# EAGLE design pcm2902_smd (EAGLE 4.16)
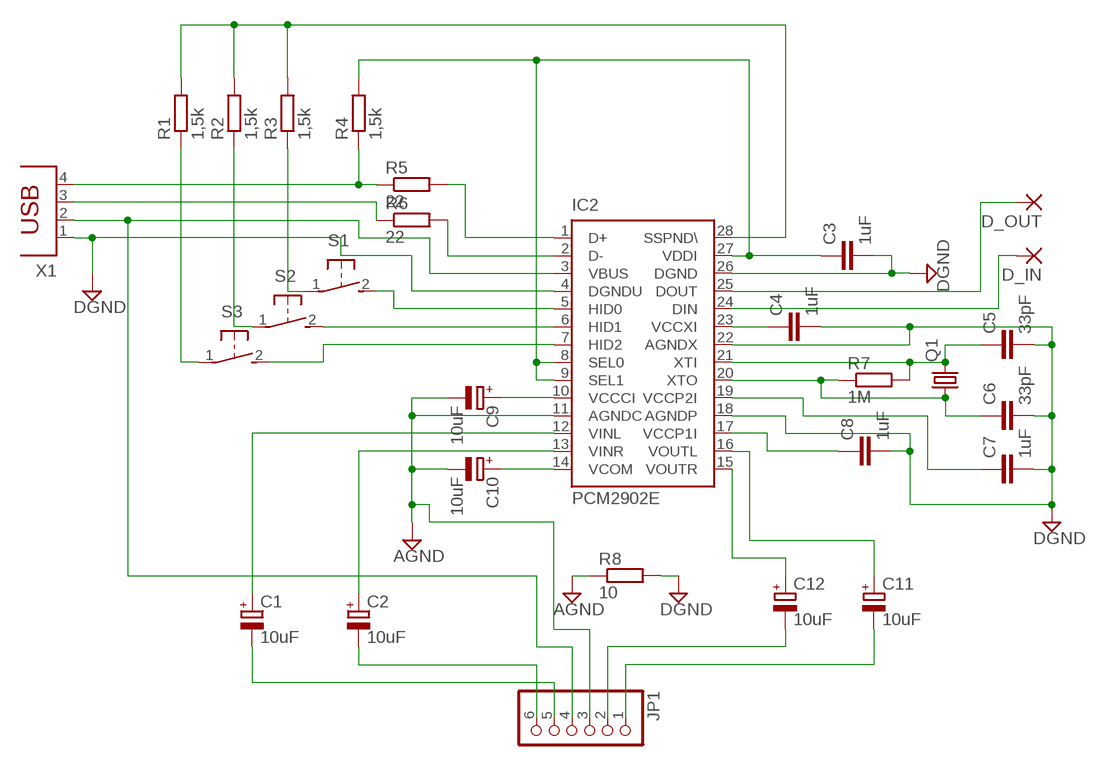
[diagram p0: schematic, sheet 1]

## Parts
C1  10uF  CPOL-EUSMCA  [SMC_A]
C2  10uF  CPOL-EUSMCA  [SMC_A]
C3  1uF  C-EUC1206  [C1206]
C4  1uF  C-EUC1206  [C1206]
C5  33pF  C-EUC1206  [C1206]
C6  33pF  C-EUC1206  [C1206]
C7  1uF  C-EUC1206  [C1206]
C8  1uF  C-EUC1206  [C1206]
C9  10uF  CPOL-EUSMCA  [SMC_A]
C10  10uF  CPOL-EUSMCA  [SMC_A]
C11  10uF  CPOL-EUSMCA  [SMC_A]
C12  10uF  CPOL-EUSMCA  [SMC_A]
D_IN  1,6/0,8  [1,6/0,8]
D_OUT  1,6/0,8  [1,6/0,8]
IC2  PCM2902E  [SSOP28DB]
JP1  PINHD-1X6  [1X06]
Q1  CRYTALSM49  [SM49]
R1  1,5k  R-EU_R1206  [R1206]
R2  1,5k  R-EU_R1206  [R1206]
R3  1,5k  R-EU_R1206  [R1206]
R4  1,5k  R-EU_R1206  [R1206]
R5  22  R-EU_R1206  [R1206]
R6  22  R-EU_R1206  [R1206]
R7  1M  R-EU_R1206  [R1206]
R8  10  R-EU_R1206  [R1206]
S1  31-XX  [B3F-31XX]
S2  31-XX  [B3F-31XX]
S3  31-XX  [B3F-31XX]
X1  PN87520  [PN87520]

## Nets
AGND: C9.- C10.- IC2.11(AGNDC) JP1.3 R8.1
D_OUT: D_OUT.1(P) IC2.25(DOUT)
DGND: C3.2 C4.2 C5.2 C6.2 C7.2 C8.2 IC2.4(DGNDU) IC2.18(AGNDP) IC2.22(AGNDX) IC2.26(DGND) R8.2 X1.1
N$1: C10.+ IC2.14(VCOM)
N$2: C9.+ IC2.10(VCCCI)
N$3: IC2.1(D+) R5.2
N$4: R4.1 R5.1 X1.4
N$5: R6.1 X1.3
N$6: IC2.2(D-) R6.2
N$7: IC2.6(HID1) S2.2(S)
N$8: C3.1 IC2.8(SEL0) IC2.9(SEL1) IC2.27(VDDI) R4.2
N$9: IC2.7(HID2) S3.2(S)
N$10: IC2.5(HID0) S1.2(S)
N$11: R1.1 S3.1(P)
N$12: R2.1 S2.1(P)
N$13: R3.1 S1.1(P)
N$14: C4.1 IC2.23(VCCXI)
N$15: IC2.28(SSPND\) R1.2 R2.2 R3.2
N$16: C1.+ IC2.12(VINL)
N$17: C2.+ IC2.13(VINR)
N$18: C5.1 IC2.21(XTI) Q1.2 R7.2
N$19: C6.1 IC2.20(XTO) Q1.1 R7.1
N$20: C7.1 IC2.19(VCCP2I)
N$21: C8.1 IC2.17(VCCP1I)
N$22: C11.- JP1.1
N$23: D_IN.1(P) IC2.24(DIN)
N$24: C11.+ IC2.16(VOUTL)
N$25: C12.+ IC2.15(VOUTR)
N$26: IC2.3(VBUS) JP1.4 X1.2
N$27: C12.- JP1.2
N$28: C1.- JP1.5
N$29: C2.- JP1.6

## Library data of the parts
C1 C2 C9-C12 = rcl:CPOL-EU: POLARIZED CAPACITOR, European symbol
C3-C8 = rcl:C-EU: CAPACITOR, European symbol
D_IN D_OUT = wirepad:1,6/0,8: THROUGH-HOLE PAD
IC2 = texas:PCM290*: STEREO AUDIO CODEC WITH USB INTERFACE SINGLE-ENDED ANALOG INPUT/OUTPUT AND S/PDIF
JP1 = pinhead:PINHD-1X6: PIN HEADER
Q1 = crystal:CRYTAL: CRYSTAL
R1-R8 = rcl:R-EU_: RESISTOR, European symbol
S1-S3 = switch-omron:31-XX: OMRON SWITCH
X1 = con-berg:PN87520: BERG USB connector

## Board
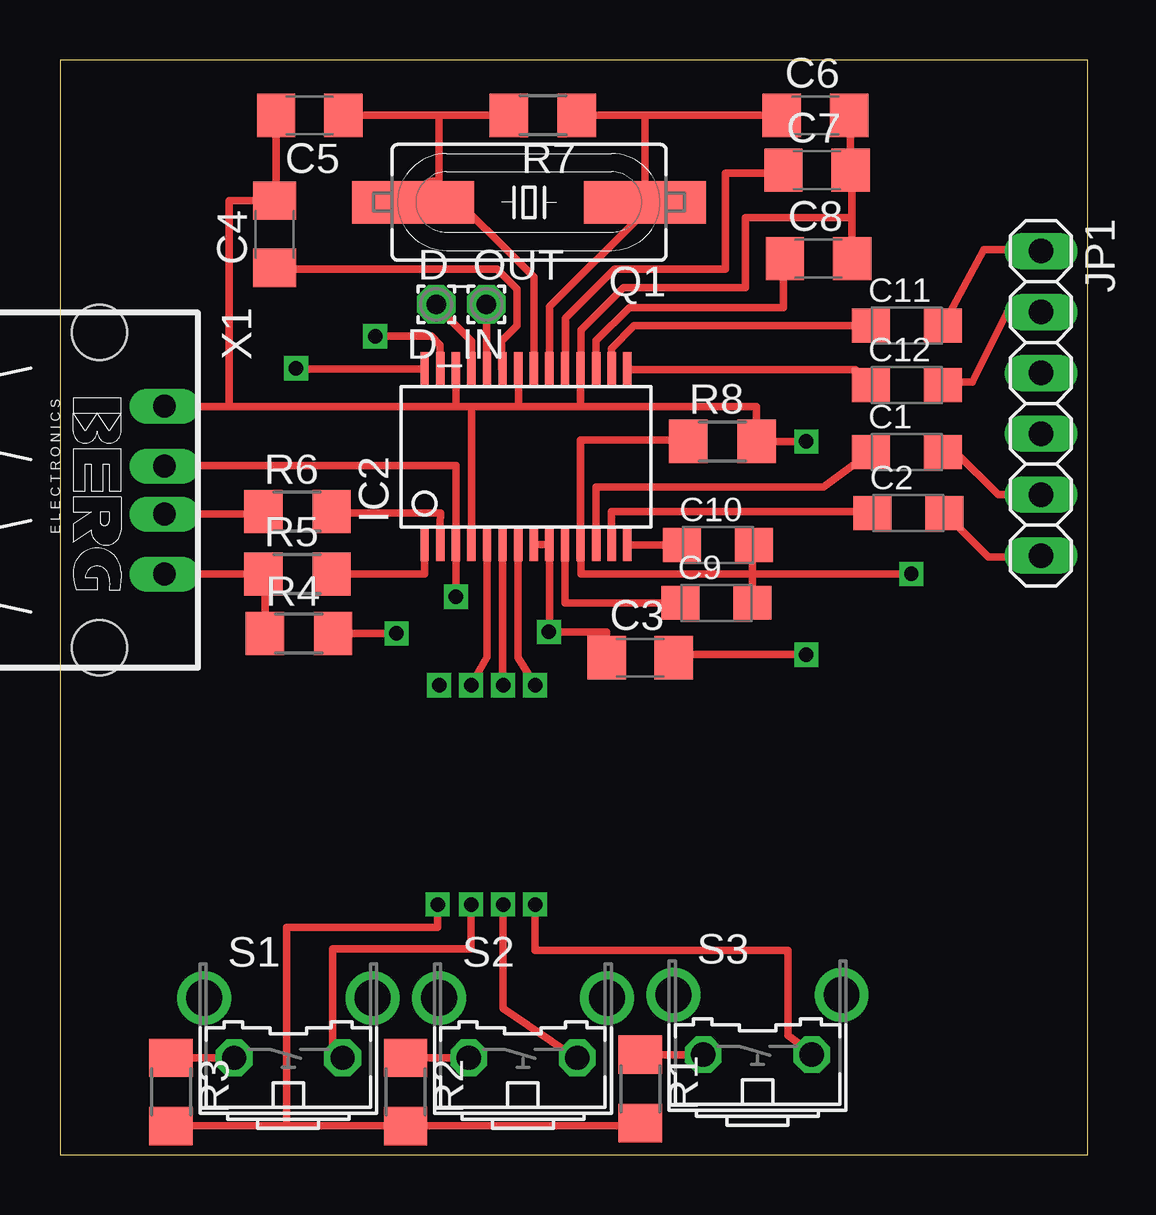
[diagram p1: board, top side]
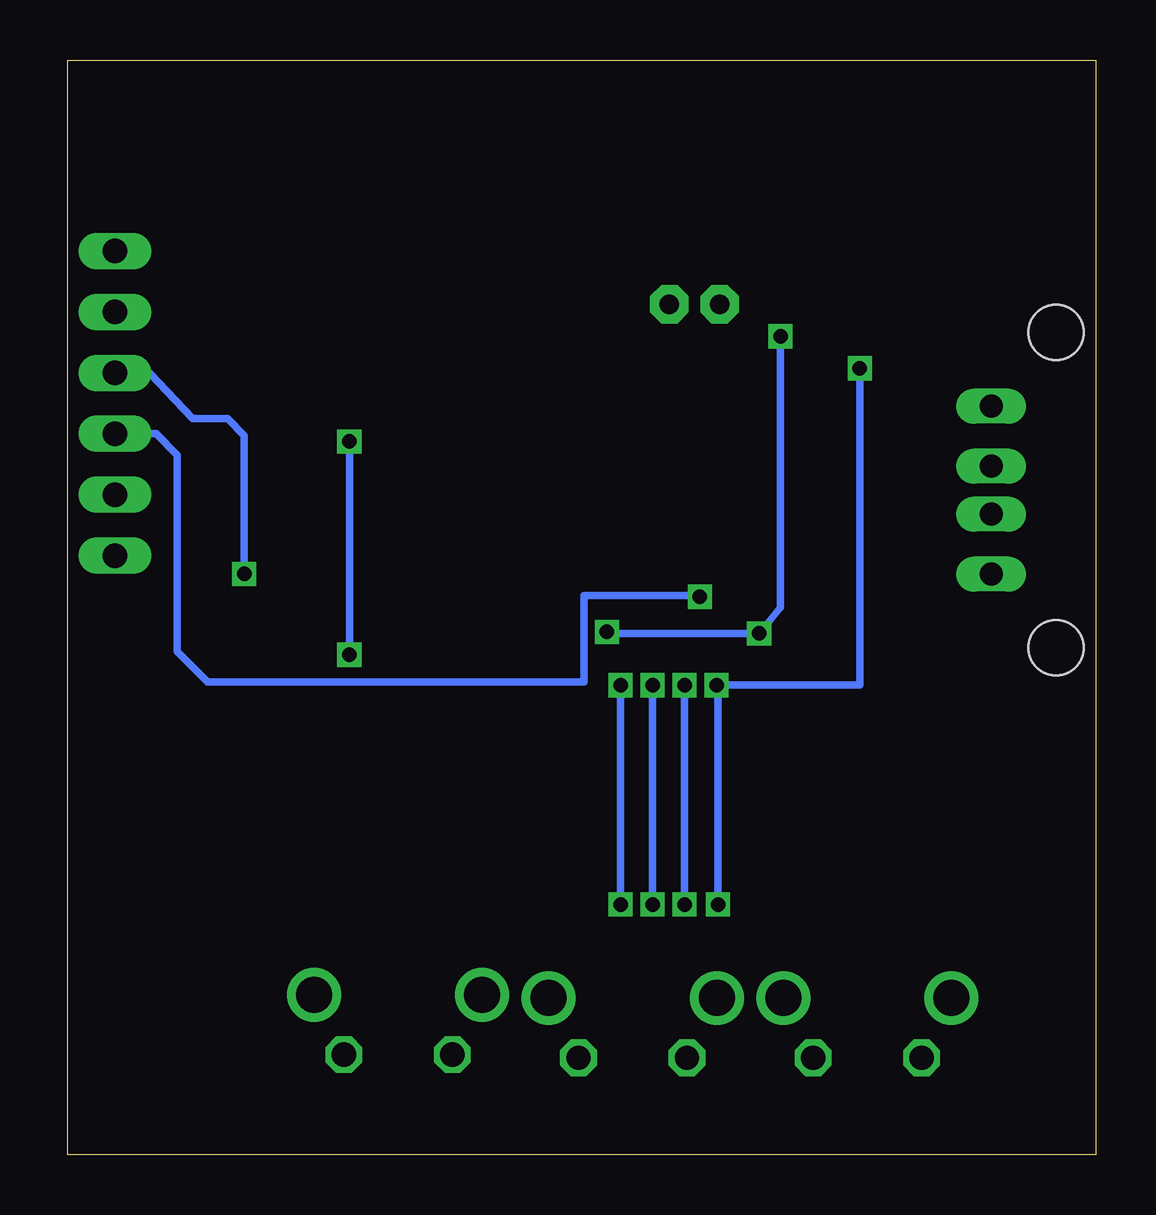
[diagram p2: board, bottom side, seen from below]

Size 42.84 x 45.64 mm. Coordinates in mm from the lower left corner, seen from the top.
Outline: 0,0 42.84,0 42.84,45.64 0,45.64 0,0
Copper layers (1*16): Top 0.035mm / dielectric 1.5mm / Bottom 0.035mm
Design rules "default": minimum track width 10mil, minimum drill 24mil, track to track 8mil, track to pad 8mil, pad to pad 8mil, via to via 8mil, smd to smd 8mil, copper to edge 40mil, drill to drill 8mil, minimum pad ring 10mil, minimum via ring 8mil, stop-mask expansion 4mil, vias tented up to drill 0mil, thermal gap 10mil

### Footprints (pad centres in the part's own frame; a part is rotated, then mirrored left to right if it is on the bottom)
SMC_A = smd 1.6 x 1.4: + -1.5,0; - 1.5,0
C1206 = smd 1.6 x 1.8: 1 -1.4,0; 2 1.4,0
1,6/0,8 = drill 0.813 pad 1.6 octagon: 1 0,0
SSOP28DB = smd 0.348 x 1.397: 1 -4.225,-3.656; 2 -3.575,-3.656; 3 -2.925,-3.656; 4 -2.275,-3.656; 5 -1.625,-3.656; 6 -0.975,-3.656; 7 -0.325,-3.656; 8 0.325,-3.656; 9 0.975,-3.656; 10 1.625,-3.656; 11 2.275,-3.656; 12 2.925,-3.656; 13 3.575,-3.656; 14 4.225,-3.656; 15 4.225,3.656; 16 3.575,3.656; 17 2.925,3.656; 18 2.275,3.656; 19 1.625,3.656; 20 0.975,3.656; 21 0.325,3.656; 22 -0.325,3.656; 23 -0.975,3.656; 24 -1.625,3.656; 25 -2.275,3.656; 26 -2.925,3.656; 27 -3.575,3.656; 28 -4.225,3.656
1X06 = drill 1.016 long: 1 -6.35,0; 2 -3.81,0; 3 -1.27,0; 4 1.27,0; 5 3.81,0; 6 6.35,0
SM49 = smd 5.08 x 1.778: 1 -4.826,0; 2 4.826,0
R1206 = smd 1.6 x 1.803: 1 -1.422,0; 2 1.422,0
B3F-31XX = drill 1.016 octagon: 1 -2.261,-1.245; 2 2.261,-1.245 | drill 1.499 pad 2.159 round: 3 -3.505,1.245; 4 3.505,1.245
PN87520 = drill 0.95 long: 1 -3.5,2.71; 2 -1,2.71; 3 1,2.71; 4 3.5,2.71 | hole 2.3: -6.57,0; 6.57,0

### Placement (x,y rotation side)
C1  35.3,29.3 0 top
C2  35.36,26.76 0 top
C3  24.19,20.73 0 top
C4  8.95,38.38 90 top
C5  10.41,43.33 180 top
C6  31.49,43.33 0 top
C7  31.55,41.05 0 top
C8  31.62,37.36 0 top
C9  27.36,23.01 0 top
C10  27.43,25.43 0 top
C11  35.3,34.57 0 top
C12  35.3,32.09 0 top
D_IN  17.77,35.46 180 top
D_OUT  15.68,35.46 0 top
IC2  19.43,29.11 0 top
JP1  40.89,31.33 270 top
Q1  19.55,39.71 180 top
R1  24.19,2.76 270 top
R2  14.41,2.63 270 top
R3  4.63,2.63 270 top
R4  9.96,21.74 0 top
R5  9.9,24.22 0 top
R6  9.9,26.82 0 top
R7  20.12,43.33 180 top
R8  27.62,29.74 0 top
S1  9.52,5.3 0 top
S2  19.3,5.3 0 top
S3  29.08,5.42 0 top
X1  1.65,27.71 270 top

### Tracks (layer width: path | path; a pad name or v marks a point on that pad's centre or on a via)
AGND  (via drill 0.6)
  Top 0.305: 26.2,29.71 26.22,29.68 | 26.2,29.71 R8.1 | 26.2,29.71 26.09,29.81 24.51,29.81 21.7,29.8 IC2.11 21.7,25.17 21.71,25.17 21.71,24.22 28.86,24.22 | 28.95,25.43 C10.- 28.86,25.43 28.86,24.22 | 28.86,24.22 C9.- | 28.86,24.22 v35.49,24.22
  Bottom 0.305: v35.49,24.22 35.49,30 36.19,30.7 37.65,30.7 39.43,32.6 JP1.3
D_OUT
  Top 0.305: D_OUT.1 15.68,35.39 17.15,33.92 IC2.25
DGND  (via drill 0.6)
  Top 0.305: v31.11,29.74 R8.2 29.04,31.2 21.65,31.2 | 19.23,31.2 19.11,31.2 19.11,32.73 19.1,32.73 IC2.22 | 19.23,31.2 21.65,31.2 | 21.65,31.2 21.7,31.27 IC2.18 21.7,33.03 21.71,33.05 21.71,34.38 23.49,36.16 28.57,36.16 28.57,39.08 33.02,39.08 33.02,39.14 | C5.2 9.01,43.46 9.01,39.78 C4.2 7.04,39.78 7.04,31.2 | C7.2 32.95,40.98 | C7.2 33.02,41.05 33.02,39.14 | C6.2 32.95,43.27 C7.2 | C8.2 33.02,37.24 | C8.2 | 33.02,39.14 C8.2 | X1.1 7.04,31.2 | 7.04,31.2 16.5,31.2 | 16.5,31.2 17.14,31.2 | 17.14,31.2 19.23,31.2 | IC2.26 16.5,31.2 | IC2.4 17.15,31.2 17.14,31.2 | C3.2 25.59,20.85 v31.11,20.85
  Bottom 0.305: v31.11,29.74 v31.11,20.85
N$1
  Top 0.305: IC2.14 23.65,25.43 C10.+
N$2
  Top 0.305: 25.9,23.33 C9.+ 21.05,23.01 IC2.10
N$3
  Top 0.305: IC2.1 15.2,24.22 R5.2
N$4
  Top 0.305: 8.44,24.22 8.38,24.22 8.38,24.16 | 8.44,24.22 R5.1 8.5,24.22 8.5,24.21 | R4.1 8.54,24.12 8.44,24.22 | X1.4 8.5,24.21 | 8.5,24.21 8.5,24.09
N$5
  Top 0.305: R6.1 8.12,26.7 8.12,26.71 4.38,26.71 | X1.3 4.38,26.71 | 4.38,26.71 4.38,26.76
N$6
  Top 0.305: IC2.2 15.85,26.27 15.87,26.76 12.25,26.76 | 12.25,26.76 12.12,26.76 | R6.2 11.74,26.76 12.25,26.76
N$7  (via drill 0.6)
  Top 0.305: IC2.6 18.45,19.67 v18.47,19.58 | S2.2 21.53,4.03 18.47,6.12 v18.47,10.44
  Bottom 0.305: v18.47,19.58 v18.47,10.44
N$8  (via drill 0.6)
  Top 0.305: 19.75,25.43 19.74,25.43 | IC2.8 19.75,25.43 | 19.75,25.43 19.77,25.45 IC2.9 20.4,21.81 | v20.38,21.81 20.4,21.81 | 11.36,21.74 R4.2 v14.03,21.74 | IC2.27 15.85,33.76 15.49,34.13 v13.14,34.13 | C3.1 22.79,21.81 20.4,21.81
  Bottom 0.305: v20.38,21.81 20.38,21.74 v14.03,21.74 13.14,22.82 v13.14,34.13
N$9  (via drill 0.6)
  Top 0.305: IC2.7 19.1,20.73 v19.81,19.58 | v19.81,10.44 19.81,8.53 30.35,8.53 30.35,4.98 31.36,4.22 31.34,4.19 S3.2
  Bottom 0.305: v19.81,19.58 v19.81,10.44
N$10  (via drill 0.6)
  Top 0.305: IC2.5 17.8,20.75 v17.14,19.58 | v17.14,10.44 17.14,8.6 11.36,8.6 11.36,4.47 S1.2 11.81,4.03
  Bottom 0.305: v17.14,19.58 v17.14,10.44
N$11
  Top 0.305: S3.1 26.79,4.15 26.77,4.18 R1.1
N$12
  Top 0.305: R2.1 14.45,4.05 14.47,4.03 14.5,4.05 S2.1
N$13
  Top 0.305: S1.1 7.3,4.09 | R3.1 S1.1 | S1.1
N$14
  Top 0.305: IC2.23 18.41,32.81 18.41,33.93 19.05,34.57 19.05,36.09 18.22,36.92 8.88,36.92 8.88,36.98 C4.1
N$15  (via drill 0.6)
  Top 0.305: R3.2 9.46,1.21 | 9.46,1.21 14.38,1.21 14.41,1.23 R2.2 24.16,1.21 24.19,1.23 R1.2 | IC2.28 9.86,32.76 v9.84,32.79 | 9.46,1.21 9.46,9.49 15.74,9.49 v15.74,10.44
  Bottom 0.305: v9.84,32.79 9.84,19.58 v15.81,19.58 15.74,19.58 v15.74,10.44
N$16
  Top 0.305: C1.+ 31.83,27.84 22.35,27.84 IC2.12 | IC2.12 22.35,25.43 | IC2.12
N$17
  Top 0.305: C2.+ 33.42,26.82 22.98,26.82 22.98,25.47 IC2.13
N$18
  Top 0.305: 14.73,39.9 14.66,39.84 | 14.73,39.9 Q1.2 | 14.73,39.9 15.43,40.6 15.74,40.6 | IC2.21 19.75,36.59 15.74,40.6 | R7.2 18.54,43.52 18.54,43.33 15.81,43.33 | 15.81,43.33 C5.1 | 15.74,40.6 15.81,40.6 15.81,43.33
N$19
  Top 0.305: IC2.20 20.4,35.35 24.32,39.27 24.32,39.9 24.25,39.97 Q1.1 24.38,43.33 | 29.9,43.4 C6.1 24.38,43.33 | 24.38,43.33 R7.1
N$20
  Top 0.305: IC2.19 21.08,32.79 21.08,34.89 23.11,36.92 27.74,36.92 27.74,40.92 30.16,40.92 | 30.16,40.92 | 30.16,40.92 C7.1
N$21
  Top 0.305: IC2.17 22.35,33.94 23.74,35.33 30.16,35.33 30.16,37.36 C8.1
N$22
  Top 0.305: 41.02,37.74 40.95,37.74 | 40.95,37.74 JP1.1 | C11.- 38.52,37.74 40.95,37.74
N$23
  Top 0.305: IC2.24 17.77,32.76 D_IN.1
N$24
  Top 0.305: C11.+ 23.93,34.57 22.98,33.62 22.98,33.11 23,33.06 IC2.16
N$25
  Top 0.305: IC2.15 23.62,32.73 33.17,32.73 C12.+
N$26  (via drill 0.6)
  Top 0.305: X1.2 4.31,28.71 4.31,28.73 16.5,28.73 16.5,26.95 IC2.3 16.5,25.3 v16.5,23.27
  Bottom 0.305: JP1.4 39.17,30.06 38.29,29.17 38.29,20.98 37.02,19.71 21.33,19.71 21.33,23.33 16.57,23.33 v16.5,23.27
N$27
  Top 0.305: JP1.2 39.49,35.14 38.03,32.22 36.82,32.22 36.8,32.2 C12.-
N$28
  Top 0.305: C1.- 37.33,29.3 39.11,27.52 JP1.5 40.95,27.46
N$29
  Top 0.305: JP1.6 40.95,24.92 38.71,24.92 C2.-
